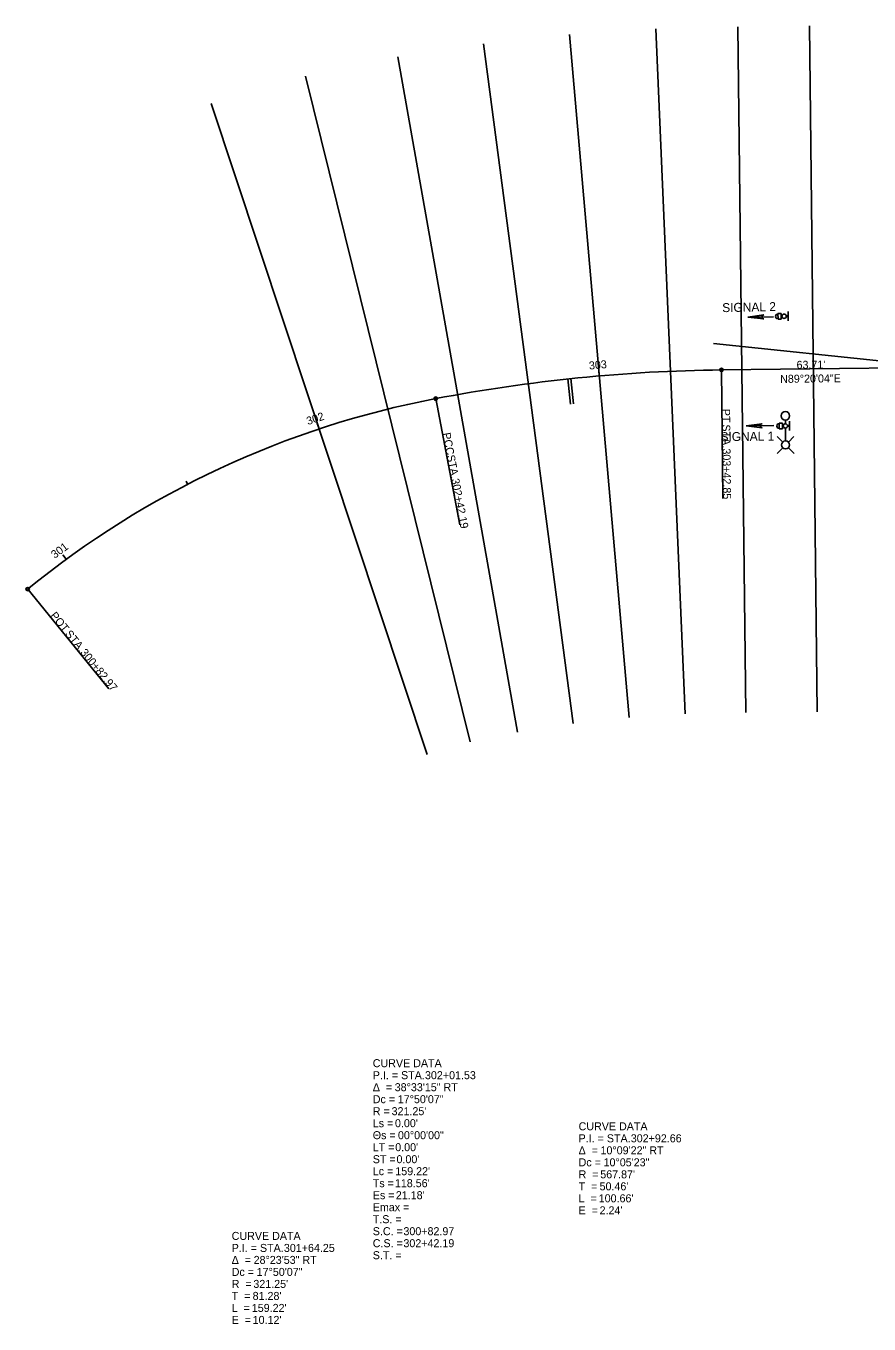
# Model space of a CAD drawing. Extents: x 153902 to 157473, y 413085 to 414252.
# Drawn here: x 153901.5 to 154196.6, y 413360.1 to 413814.4 of the extents above; entities that cross this region are included whole.
import ezdxf

# ---------------------------------------------------------------- set-up
doc = ezdxf.new("R2010")
doc.units = 0
for name, color, linetype in [('GE_P_Alignment', 7, 'Continuous'), ('GE_P_Alignment_100_Bearings', 7, 'Continuous'), ('GE_P_Alignment_100_Cardinal_Points', 7, 'Continuous'), ('GE_P_Alignment_100_Distances', 7, 'Continuous'), ('GE_P_Alignment_100_Stations', 7, 'Continuous'), ('PF_X_Ground_Line', 7, 'Continuous'), ('PM_X_Cells', 7, 'Continuous'), ('PV_X_Text', 7, 'Continuous'), ('SV_X_Text', 7, 'Continuous'), ('VG_X_Flower_Bed', 7, 'Continuous')]:
    doc.layers.add(name, color=color, linetype=linetype)

msp = doc.modelspace()

# ---------------------------------------------------------------- linework, layer by layer
at = {"layer": 'GE_P_Alignment'}
msp.add_line((154144.98, 413694.03), (154208.68, 413694.77), dxfattribs=at)
for centre, radius, start, end in [((154151.58, 413126.2), 567.87, 90.6657, 100.8218), ((154105.27, 413368.43), 321.25, 100.8218, 129.22)]:
    msp.add_arc(centre, radius, start, end, dxfattribs=at)
at = {"layer": 'GE_P_Alignment_100_Cardinal_Points'}
for p, q in [((154144.98, 413694.03), (154145.5, 413649.03)), ((154044.96, 413683.97), (154053.4, 413639.77)), ((153902.15, 413617.31), (153930.6, 413582.45))]:
    msp.add_line(p, q, dxfattribs=at)
for centre in [(154144.98, 413694.03), (154044.96, 413683.97), (153902.15, 413617.31)]:
    msp.add_circle(centre, 0.6, dxfattribs=at)
at = {"layer": 'PF_X_Ground_Line'}
for p, q in [((154102.19, 413691.92), (154102.01, 413693.91)), ((154152.12, 413694.11), (154152.11, 413695.31)), ((154052.63, 413685.38), (154052.42, 413686.56)), ((154004.15, 413673.35), (154003.52, 413675.25)), ((153958.11, 413653.99), (153957.56, 413655.06)), ((153915.62, 413627.73), (153914.44, 413629.34))]:
    msp.add_line(p, q, dxfattribs=at)
at = {"layer": 'PM_X_Cells'}
for p, q in [((154092.16, 413682.06), (154091.24, 413690.85)), ((154092.23, 413690.96), (154093.16, 413682.15))]:
    msp.add_line(p, q, dxfattribs=at)
at = {"layer": 'PV_X_Text'}
for p, q in [((154178.52, 413574.41), (154175.73, 413814.4)), ((154091.75, 413811.46), (154112.62, 413572.37)), ((154132.3, 413573.65), (154121.97, 413813.43)), ((154150.73, 413814.1), (154153.52, 413574.12)), ((154093.03, 413570.22), (154061.65, 413808.16)), ((154031.72, 413803.55), (154073.54, 413567.22)), ((154056.97, 413563.8), (153999.36, 413796.78)), ((153966.38, 413787.25), (154041.92, 413559.45))]:
    msp.add_line(p, q, dxfattribs=at)
at = {"layer": 'SV_X_Text'}
msp.add_line((154217.1, 413695.41), (154142.21, 413703.24), dxfattribs=at)
at = {"layer": 'VG_X_Flower_Bed'}
for p, q in [((154168.28, 413714.45), (154168.36, 413711.21)), ((154154.2, 413712.45), (154159.81, 413713.28)), ((154163.14, 413712.65), (154154.2, 413712.45)), ((154159.84, 413711.87), (154154.2, 413712.45)), ((154164.25, 413713.46), (154164.73, 413713.47)), ((154164.28, 413712.02), (154164.76, 413712.03)), ((154164.73, 413713.72), (154165.88, 413713.74)), ((154164.73, 413713.72), (154164.78, 413711.78)), ((154164.78, 413711.78), (154165.92, 413711.8)), ((154165.88, 413713.74), (154165.92, 413711.8)), ((154166.16, 413712.9), (154165.9, 413712.89)), ((154166.17, 413712.66), (154165.9, 413712.65)), ((154168.32, 413712.95), (154167.66, 413712.94)), ((154168.32, 413712.71), (154167.66, 413712.7)), ((154153.6, 413674.4), (154159.21, 413675.17)), ((154163.25, 413674.51), (154153.6, 413674.4)), ((154159.23, 413673.76), (154153.6, 413674.4)), ((154164.7, 413675.11), (154165.18, 413675.11)), ((154164.72, 413673.66), (154165.2, 413673.67)), ((154165.19, 413675.36), (154166.33, 413675.38)), ((154165.19, 413675.36), (154165.21, 413673.42)), ((154166.33, 413675.38), (154166.36, 413673.44)), ((154166.61, 413674.53), (154166.34, 413674.53)), ((154166.61, 413674.29), (154166.35, 413674.29)), ((154167.34, 413676.44), (154167.35, 413675.17)), ((154167.36, 413673.66), (154167.38, 413669.17)), ((154168.77, 413674.56), (154168.1, 413674.55)), ((154168.77, 413674.32), (154168.11, 413674.31)), ((154168.75, 413676.06), (154168.79, 413672.82)), ((154166.4, 413668.75), (154164.41, 413670.72)), ((154165.21, 413673.42), (154166.36, 413673.44)), ((154168.38, 413668.76), (154170.35, 413670.75)), ((154166.41, 413666.77), (154164.44, 413664.78)), ((154168.39, 413666.78), (154170.38, 413664.81))]:
    msp.add_line(p, q, dxfattribs=at)
for centre, radius in [((154166.91, 413712.8), 0.757), ((154167.33, 413677.93), 1.5), ((154167.36, 413674.42), 0.757), ((154167.39, 413667.77), 1.4)]:
    msp.add_circle(centre, radius, dxfattribs=at)
for centre, radius, start, end in [((154159.82, 413712.57), 0.702, 91.2503, 271.2503), ((154159.22, 413674.47), 0.703, 90.6595, 270.6595)]:
    msp.add_arc(centre, radius, start, end, dxfattribs=at)
for centre, major_axis in [((154164.26, 413712.74), (-0.017, 0.721)), ((154164.71, 413674.39), (-0.009, 0.721))]:
    msp.add_ellipse(centre, major_axis=major_axis, ratio=0.45371, start_param=0, end_param=3.141593, dxfattribs=at)

# ---------------------------------------------------------------- texts
at = {"layer": 'GE_P_Alignment_100_Bearings'}
msp.add_text('N89°20\'04"E', height=2.8, rotation=0.6657, dxfattribs=at).set_placement((154165.52, 413689.47))
at = {"layer": 'GE_P_Alignment_100_Cardinal_Points'}
for s, rotation, p in [('PT', 270.6657, (154145.18, 413680.39)), (' STA. ', 270.6657, (154145.23, 413675.98)), ('PCC', 280.8218, (154047.32, 413671.81)), ('303+42.85', 270.6657, (154145.34, 413666.53)), (' STA. ', 280.8218, (154048.62, 413665.05)), ('302+42.19', 280.8218, (154050.39, 413655.76)), ('POT', 309.22, (153909.85, 413607.94)), (' STA. ', 309.22, (153914.4, 413602.36)), ('300+82.97', 309.22, (153920.38, 413595.04))]:
    msp.add_text(s, height=2.8, rotation=rotation, dxfattribs=at).set_placement(p)
at = {"layer": 'GE_P_Alignment_100_Distances'}
for s, p in [('CURVE DATA', (154022.93, 413449.99)), ('P.I. = STA. ', (154022.93, 413445.79)), ('302+01.53', (154041.2, 413445.79)), ('Δ  = ', (154022.93, 413441.59)), ('38°33\'15" RT', (154030.61, 413441.59)), ('Dc = ', (154022.93, 413437.39)), ('17°50\'07"', (154031.67, 413437.39)), ('R = ', (154022.93, 413433.19)), ("321.25'", (154029.52, 413433.19)), ('Ls = ', (154022.93, 413428.99)), ("0.00'", (154030.7, 413428.99)), ('CURVE DATA', (154094.97, 413427.9)), ('Θs = ', (154022.93, 413424.79)), ('00°00\'00"', (154031.74, 413424.79)), ('P.I. = STA. ', (154094.97, 413423.7)), ('302+92.66', (154113.23, 413423.7)), ('ST = ', (154022.93, 413416.39)), ('LT = ', (154022.93, 413420.59)), ("0.00'", (154030.79, 413420.59)), ("0.00'", (154031.24, 413416.39)), ('Δ  = ', (154094.97, 413419.5)), ('10°09\'22" RT', (154102.64, 413419.5)), ('Lc = ', (154022.93, 413412.19)), ("159.22'", (154030.81, 413412.19)), ('Dc = ', (154094.97, 413415.3)), ('10°05\'23"', (154103.71, 413415.3)), ('Ts = ', (154022.93, 413407.99)), ("118.56'", (154030.67, 413407.99)), ('R  = ', (154094.97, 413411.1)), ("567.87'", (154102.55, 413411.1)), ('Es = ', (154022.93, 413403.79)), ("21.18'", (154031, 413403.79)), ('T  = ', (154094.97, 413406.9)), ('L  = ', (154094.97, 413402.7)), ("100.66'", (154102.01, 413402.7)), ("50.46'", (154102.31, 413406.9)), ('Emax = ', (154022.93, 413399.59)), ('E  = ', (154094.97, 413398.5)), ("2.24'", (154102.31, 413398.5)), ('T.S. = ', (154022.93, 413395.39)), ('CURVE DATA', (153973.55, 413389.54)), ('S.C. = ', (154022.93, 413391.19)), ('300+82.97', (154033.66, 413391.19)), ('P.I. = STA. ', (153973.55, 413385.34)), ('301+64.25', (153991.82, 413385.34)), ('C.S. = ', (154022.93, 413386.99)), ('302+42.19', (154033.66, 413386.99)), ('Δ  = ', (153973.55, 413381.14)), ('28°23\'53" RT', (153981.23, 413381.14)), ('S.T. = ', (154022.93, 413382.79)), ('Dc = ', (153973.55, 413376.94)), ('17°50\'07"', (153982.29, 413376.94)), ('R  = ', (153973.55, 413372.74)), ("321.25'", (153981.13, 413372.74)), ('T  = ', (153973.55, 413368.54)), ("81.28'", (153980.89, 413368.54)), ('L  = ', (153973.55, 413364.34)), ("159.22'", (153980.59, 413364.34)), ('E  = ', (153973.55, 413360.14)), ("10.12'", (153980.89, 413360.14))]:
    msp.add_text(s, height=2.8, dxfattribs=at).set_placement(p)
at = {"layer": 'GE_P_Alignment_100_Stations'}
msp.add_text("63.71'", height=2.8, rotation=0.6657, dxfattribs=at).set_placement((154171.27, 413694.38))
at = {"layer": 'PF_X_Ground_Line'}
for s, rotation, p in [('303', 4.9894, (154098.71, 413694.12)), ('302', 18.3472, (154000.25, 413674.69)), ('301', 36.1826, (153911.6, 413627.88))]:
    msp.add_text(s, height=2.8, rotation=rotation, dxfattribs=at).set_placement(p)
at = {"layer": 'VG_X_Flower_Bed'}
for s, rotation, p in [('SIGNAL 2', 1.2503, (154145.26, 413714.23)), ('SIGNAL 1', 0.6595, (154144.65, 413669.07))]:
    msp.add_text(s, height=3.125, rotation=rotation, dxfattribs=at).set_placement(p)

doc.saveas('drawing.dxf')
